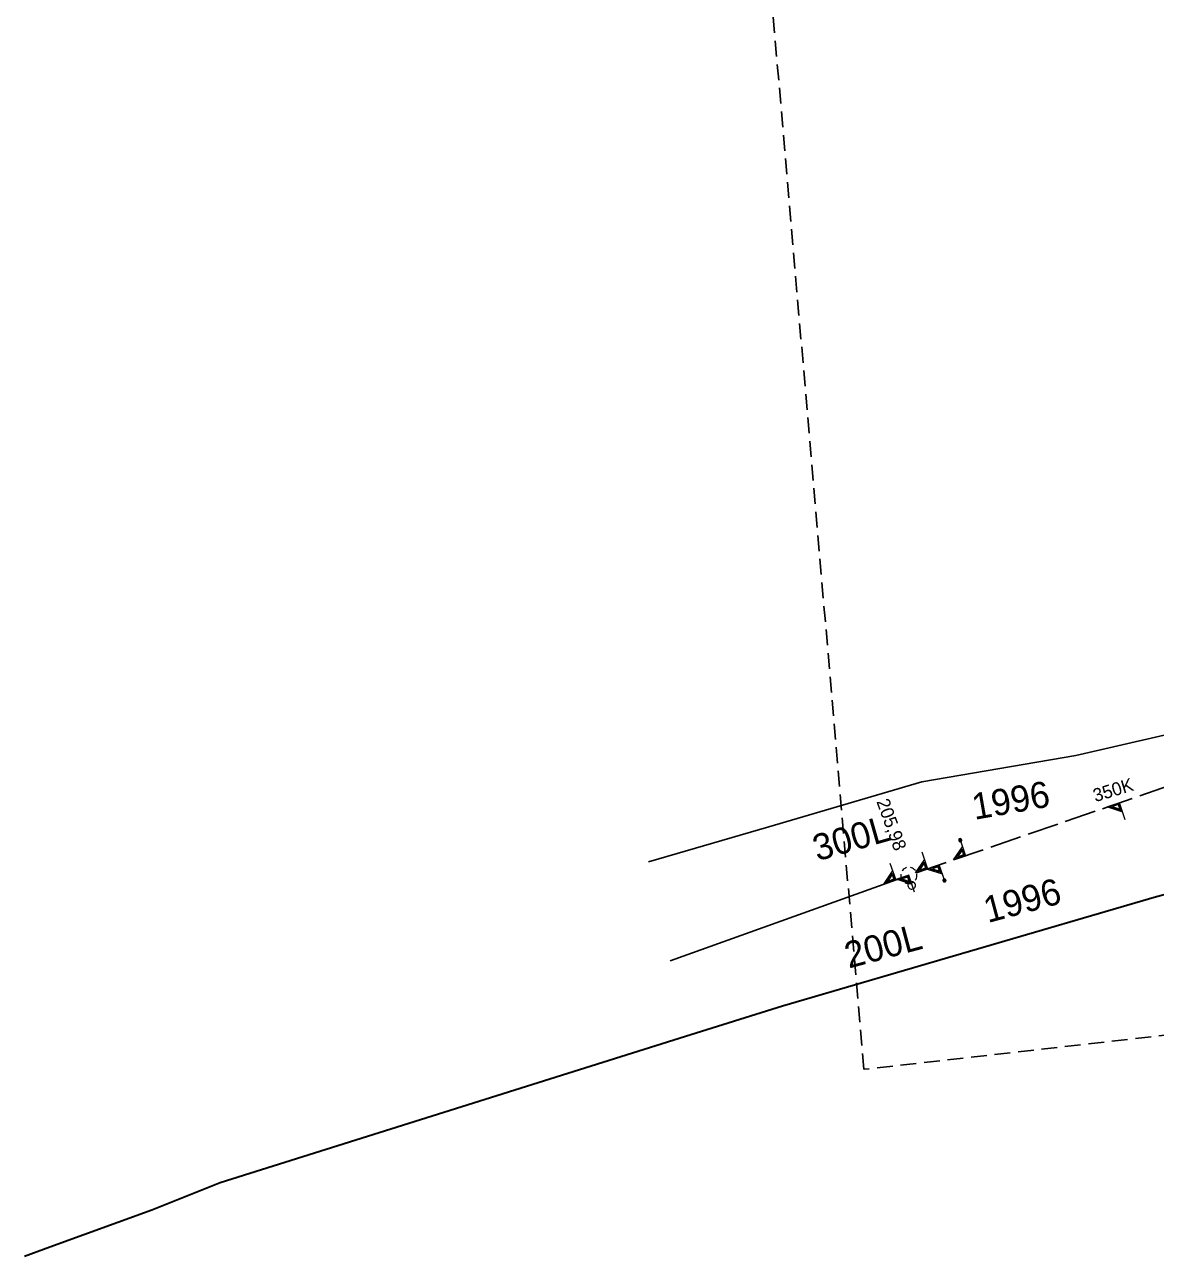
# Model space of a CAD drawing. Extents: x -740786 to -740000, y -1046854 to -1046100.
# Drawn here: x -740640.2 to -740571.3, y -1046816 to -1046741 of the extents above; entities that cross this region are included whole.
import ezdxf

# ---------------------------------------------------------------- set-up
doc = ezdxf.new("R2010")
doc.units = 0
doc.header["$LTSCALE"] = 0.32
doc.linetypes.add('LONG_DASHED', pattern=[7.5, 6, -1.5])
doc.linetypes.add('MEDIUM_DASHED', pattern=[4.5, 3, -1.5])
doc.layers.add('1', color=7, linetype='Continuous')
doc.layers.add('15', color=7, linetype='Continuous')
for name, color, linetype, lineweight in [('18', 7, 'Continuous', 13), ('20', 7, 'LONG_DASHED', 25), ('63', 7, 'MEDIUM_DASHED', 25), ('8', 7, 'Continuous', 13)]:
    doc.layers.add(name, color=color, linetype=linetype, lineweight=lineweight)

msp = doc.modelspace()

# ---------------------------------------------------------------- linework, layer by layer
at = {"layer": '18'}
for points in [[(-740573.125, -1046789.425), (-740573.481, -1046788.388), (-740574.21, -1046788.639), (-740573.293, -1046788.935)], [(-740573.38, -1046788.84), (-740573.515, -1046788.447), (-740574.049, -1046788.63), (-740573.379, -1046788.841)], [(-740583.213, -1046790.575), (-740582.857, -1046791.611), (-740583.585, -1046791.861), (-740583.045, -1046791.064)], [(-740583.054, -1046791.192), (-740582.919, -1046791.586), (-740583.454, -1046791.77), (-740583.054, -1046791.191)], [(-740585.53, -1046791.377), (-740585.173, -1046792.413), (-740585.901, -1046792.663), (-740585.361, -1046791.866)], [(-740585.37, -1046791.994), (-740585.235, -1046792.388), (-740585.77, -1046792.572), (-740585.371, -1046791.993)], [(-740583.071, -1046791.287), (-740582.976, -1046791.563), (-740583.328, -1046791.684), (-740583.07, -1046791.287)], [(-740587.478, -1046792.057), (-740587.108, -1046793.089), (-740587.833, -1046793.348), (-740587.303, -1046792.545)], [(-740587.31, -1046792.673), (-740587.17, -1046793.064), (-740587.703, -1046793.255), (-740587.311, -1046792.672)], [(-740586.798, -1046792.729), (-740586.804, -1046792.806), (-740586.799, -1046792.883), (-740586.782, -1046792.958), (-740586.753, -1046793.029), (-740586.713, -1046793.095), (-740586.697, -1046793.117)], [(-740586.453, -1046792.337), (-740586.524, -1046792.365), (-740586.591, -1046792.404), (-740586.651, -1046792.452), (-740586.702, -1046792.509), (-740586.726, -1046792.543)], [(-740585.912, -1046792.52), (-740585.962, -1046792.462), (-740586.02, -1046792.412), (-740586.085, -1046792.371), (-740586.156, -1046792.342), (-740586.205, -1046792.328)], [(-740585.917, -1046793.106), (-740585.876, -1046793.041), (-740585.845, -1046792.971), (-740585.826, -1046792.896), (-740585.818, -1046792.82), (-740585.823, -1046792.743), (-740585.829, -1046792.708)], [(-740585.387, -1046792.089), (-740585.293, -1046792.364), (-740585.644, -1046792.485), (-740585.386, -1046792.089)], [(-740584.109, -1046793.206), (-740584.465, -1046792.17), (-740585.194, -1046792.421), (-740584.277, -1046792.717)], [(-740584.364, -1046792.621), (-740584.499, -1046792.227), (-740585.034, -1046792.412), (-740584.363, -1046792.623)], [(-740584.435, -1046792.558), (-740584.53, -1046792.282), (-740584.881, -1046792.402), (-740584.434, -1046792.557)], [(-740587.326, -1046792.768), (-740587.228, -1046793.042), (-740587.579, -1046793.167), (-740587.325, -1046792.767)], [(-740585.97, -1046793.842), (-740586.304, -1046792.798), (-740587.038, -1046793.033), (-740586.128, -1046793.349)], [(-740586.213, -1046793.252), (-740586.339, -1046792.856), (-740586.877, -1046793.028), (-740586.212, -1046793.253)], [(-740586.283, -1046793.186), (-740586.372, -1046792.909), (-740586.725, -1046793.022), (-740586.282, -1046793.186)], [(-740586.54, -1046793.246), (-740586.47, -1046793.277), (-740586.395, -1046793.296), (-740586.319, -1046793.303), (-740586.242, -1046793.298), (-740586.167, -1046793.281), (-740586.095, -1046793.253), (-740586.035, -1046793.218)]]:
    msp.add_lwpolyline(points, dxfattribs=at)
for points in [[(-740573.451, -1046788.776), (-740573.546, -1046788.501), (-740573.897, -1046788.621)], [(-740583.271, -1046790.695), (-740583.255, -1046790.724), (-740583.23, -1046790.746), (-740583.198, -1046790.757), (-740583.165, -1046790.756), (-740583.134, -1046790.745), (-740583.109, -1046790.722), (-740583.092, -1046790.693), (-740583.088, -1046790.659), (-740583.096, -1046790.627), (-740583.114, -1046790.599), (-740583.141, -1046790.579), (-740583.174, -1046790.57), (-740583.206, -1046790.573), (-740583.238, -1046790.587), (-740583.261, -1046790.611), (-740583.274, -1046790.642), (-740583.276, -1046790.675)], [(-740583.246, -1046790.687), (-740583.231, -1046790.712), (-740583.208, -1046790.728), (-740583.18, -1046790.732), (-740583.153, -1046790.726), (-740583.13, -1046790.709), (-740583.118, -1046790.683), (-740583.116, -1046790.655), (-740583.126, -1046790.629), (-740583.145, -1046790.609), (-740583.172, -1046790.599), (-740583.2, -1046790.601), (-740583.225, -1046790.613), (-740583.243, -1046790.636), (-740583.25, -1046790.663)], [(-740585.909, -1046793.419), (-740585.915, -1046793.367), (-740585.933, -1046793.317), (-740585.961, -1046793.273), (-740585.999, -1046793.236), (-740586.044, -1046793.209), (-740586.094, -1046793.193), (-740586.146, -1046793.188), (-740586.198, -1046793.195), (-740586.247, -1046793.214), (-740586.291, -1046793.244), (-740586.326, -1046793.283), (-740586.352, -1046793.328), (-740586.367, -1046793.379), (-740586.37, -1046793.431), (-740586.362, -1046793.483), (-740586.341, -1046793.531), (-740586.311, -1046793.574), (-740586.271, -1046793.609), (-740586.225, -1046793.633), (-740586.174, -1046793.647), (-740586.122, -1046793.649), (-740586.07, -1046793.639), (-740586.022, -1046793.617), (-740585.98, -1046793.585), (-740585.947, -1046793.545), (-740585.923, -1046793.498), (-740585.911, -1046793.447)], [(-740584.229, -1046793.148), (-740584.213, -1046793.177), (-740584.187, -1046793.199), (-740584.156, -1046793.21), (-740584.122, -1046793.209), (-740584.092, -1046793.198), (-740584.066, -1046793.175), (-740584.05, -1046793.145), (-740584.046, -1046793.112), (-740584.053, -1046793.08), (-740584.072, -1046793.051), (-740584.099, -1046793.032), (-740584.131, -1046793.023), (-740584.164, -1046793.026), (-740584.195, -1046793.04), (-740584.218, -1046793.064), (-740584.232, -1046793.095), (-740584.234, -1046793.128)], [(-740584.204, -1046793.137), (-740584.19, -1046793.162), (-740584.166, -1046793.178), (-740584.139, -1046793.183), (-740584.111, -1046793.176), (-740584.089, -1046793.159), (-740584.075, -1046793.134), (-740584.073, -1046793.106), (-740584.084, -1046793.079), (-740584.104, -1046793.059), (-740584.13, -1046793.049), (-740584.159, -1046793.051), (-740584.183, -1046793.063), (-740584.201, -1046793.086), (-740584.208, -1046793.114)]]:
    msp.add_lwpolyline(points, close=True, dxfattribs=at)
at = {"layer": '20'}
msp.add_line((-740561.35, -1046784.22), (-740586.3, -1046792.8), dxfattribs=at)
msp.add_line((-740561.35, -1046784.22), (-740586.3, -1046792.8), dxfattribs=at)
at = {"layer": '20', "linetype": 'Continuous'}
msp.add_line((-740586.3, -1046792.8), (-740600.859, -1046798.01), dxfattribs=at)
msp.add_line((-740586.3, -1046792.8), (-740600.859, -1046798.01), dxfattribs=at)
at = {"layer": '63'}
msp.add_lwpolyline([(-740455.336, -1046482.714), (-740468.522, -1046790.977), (-740468.522, -1046790.979), (-740468.523, -1046790.981), (-740468.524, -1046790.982), (-740468.525, -1046790.984), (-740468.527, -1046790.985), (-740468.529, -1046790.986), (-740468.531, -1046790.986), (-740589.04, -1046804.624), (-740589.042, -1046804.624), (-740589.044, -1046804.624), (-740589.046, -1046804.623), (-740589.047, -1046804.622), (-740589.049, -1046804.621), (-740589.05, -1046804.619), (-740589.05, -1046804.617), (-740589.051, -1046804.615), (-740596.533, -1046717.763), (-740626.694, -1046502.274)], dxfattribs=at)
at = {"layer": '8', "lineweight": 25}
msp.add_lwpolyline([(-740602.17, -1046791.99), (-740594.85, -1046789.86), (-740585.52, -1046787.11), (-740576.14, -1046785.51), (-740565.64, -1046783.08), (-740553.969, -1046779.61), (-740548.899, -1046778.149)], dxfattribs=at)
at = {"layer": '8', "lineweight": 35}
msp.add_lwpolyline([(-740530.873, -1046785.006), (-740538.71, -1046786.66), (-740555.71, -1046790.05), (-740571.23, -1046794.11), (-740594, -1046800.78), (-740599.92, -1046802.62), (-740628.26, -1046811.55), (-740632.43, -1046813.2), (-740638.649, -1046815.45), (-740640.18, -1046816.02)], dxfattribs=at)

# ---------------------------------------------------------------- texts
at = {"layer": '1'}
for s, rotation, p in [('350K', 17, (-740574.952, -1046788.351)), ('205,98', 290, (-740588.299, -1046788.306))]:
    msp.add_text(s, height=0.8, rotation=rotation, dxfattribs=at).set_placement(p)
at = {"layer": '15'}
for s, rotation, p in [('1996', 10, (-740582.313, -1046789.43)), ('300L', 16, (-740591.888, -1046791.958)), ('1996', 15, (-740581.502, -1046795.718)), ('200L', 15, (-740589.975, -1046798.49))]:
    msp.add_text(s, height=1.6, rotation=rotation, dxfattribs=at).set_placement(p)

doc.saveas('drawing.dxf')
